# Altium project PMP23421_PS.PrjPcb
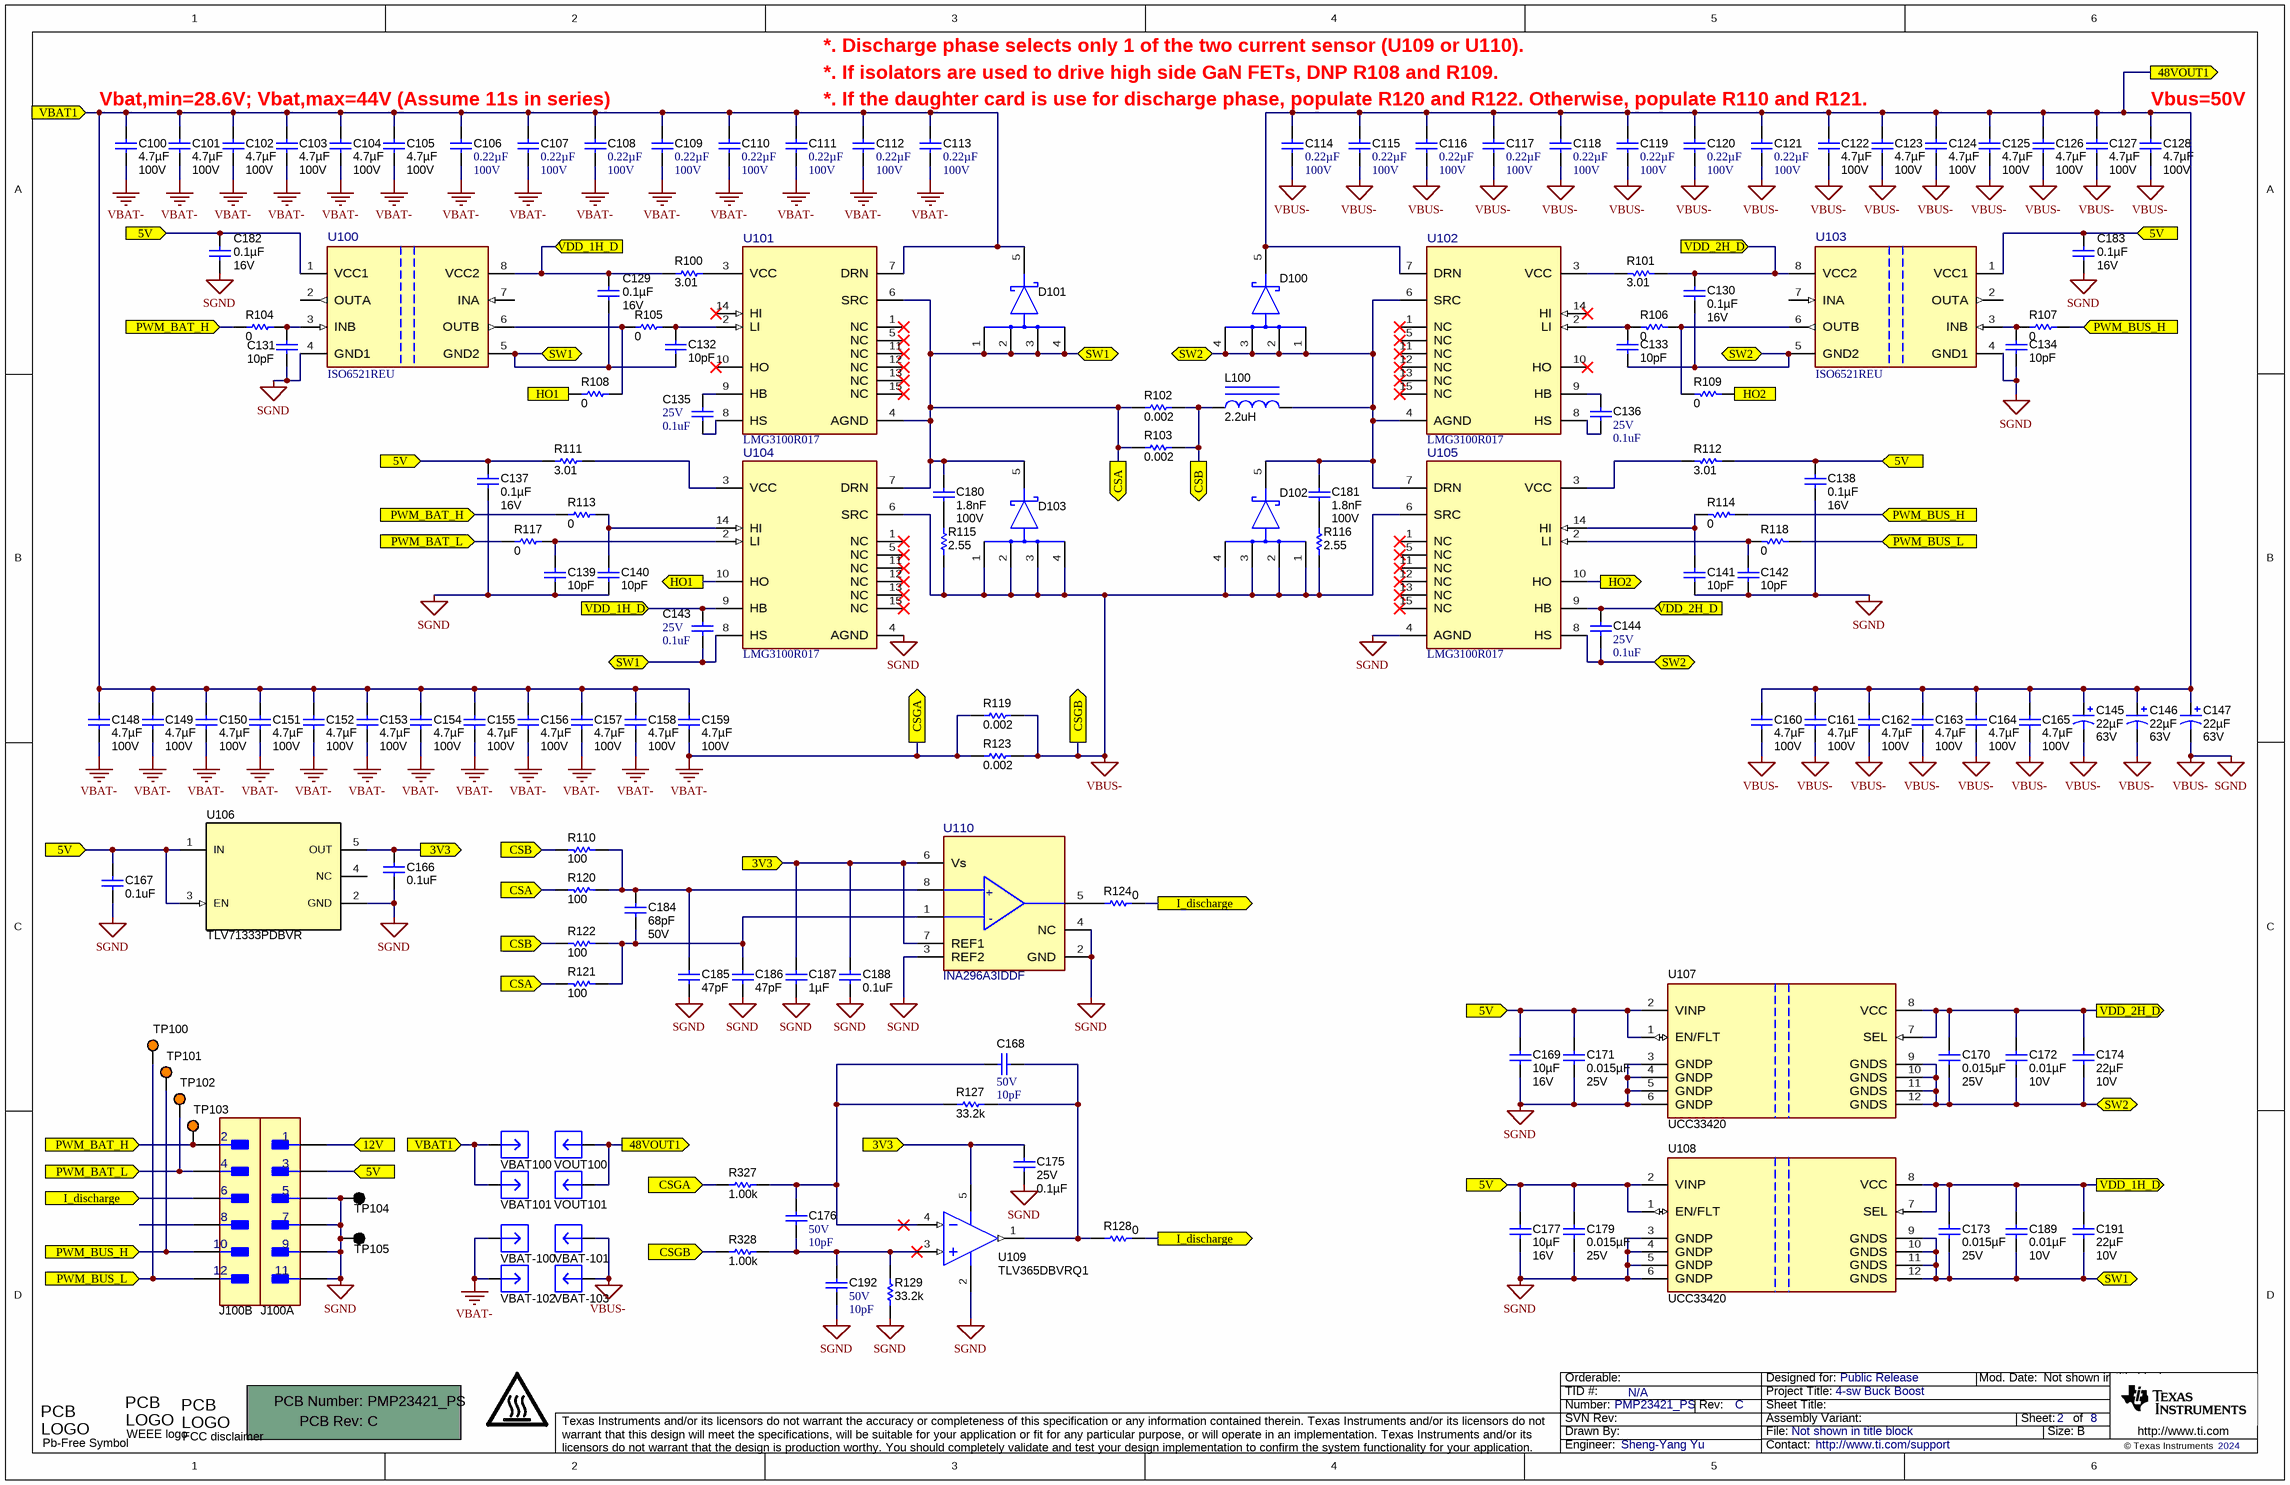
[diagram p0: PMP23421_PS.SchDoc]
CopyrightYear: 2024; PCB_Layout: Sheng-Yang Yu; PCB_Rev: C; PRJ_Customer: Public Release; PRJ_Engineer: Sheng-Yang Yu; PRJ_Number: PMP23421_PS; PRJ_Title: 4-sw Buck Boost; SCH_Rev: C; TechSupport: http://www.ti.com/support; TID: N/A
1 sheet, 157 parts. Net scope: flat (ports and power ports of the same name join across sheets).
Board file: PMP23421_PS.PcbDoc

## Sheet PMP23421_PS.SchDoc
size 431 x 279 mm; Date: Not shown in title block; ApprovedBy: Not shown in title block; CheckedBy: Not shown in title block; Author: Not shown in title block; CompanyName: Not shown in title block; Engineer: Not shown in title block; Organization: Not shown in title block; Address1: Not shown in title block; Address2: Not shown in title block; Address3: Not shown in title block; Address4: Not shown in title block; DocumentNumber: 2; Revision: Use project parameter SCH_Rev; SheetNumber: 2; SheetTotal: 8; PageSetup: Record=PageOptions¦CenterHorizontal=True¦CenterVertical=True¦PrintScale=1.00¦XCorrection=1.00¦YCorrection=1.00¦PrintKind=0¦BorderSize=5000000¦LeftOffset=0¦BottomOffset=0¦Orientation=2¦PaperLength=1000¦PaperWidth=1000¦Scale=100¦PaperSource=15¦PrintQuality=600¦MediaType=1¦DitherType=10¦PaperKind=Letter¦PrintScaleMode=1

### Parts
!PCB100  Printed Circuit Board  (value not drawn)  (mechanical)
C100  ValueDisplayed: 4.7µF  Value2: 100V  [1206_180]  (hidden comment: GRJ31CC72A475KE01L)
C101  ValueDisplayed: 4.7µF  Value2: 100V  [1206_180]  (hidden comment: GRJ31CC72A475KE01L)
C102  ValueDisplayed: 4.7µF  Value2: 100V  [1206_180]  (hidden comment: GRJ31CC72A475KE01L)
C103  ValueDisplayed: 4.7µF  Value2: 100V  [1206_180]  (hidden comment: GRJ31CC72A475KE01L)
C104  ValueDisplayed: 4.7µF  Value2: 100V  [1206_180]  (hidden comment: GRJ31CC72A475KE01L)
C105  ValueDisplayed: 4.7µF  Value2: 100V  [1206_180]  (hidden comment: GRJ31CC72A475KE01L)
C106  ValueDisplayed: 0.22µF  Value2: 100V  [0603]  (hidden comment: MBASH168SC7224KTCA01)
C107  ValueDisplayed: 0.22µF  Value2: 100V  [0603]  (hidden comment: MBASH168SC7224KTCA01)
C108  ValueDisplayed: 0.22µF  Value2: 100V  [0603]  (hidden comment: MBASH168SC7224KTCA01)
C109  ValueDisplayed: 0.22µF  Value2: 100V  [0603]  (hidden comment: MBASH168SC7224KTCA01)
C110  ValueDisplayed: 0.22µF  Value2: 100V  [0603]  (hidden comment: MBASH168SC7224KTCA01)
C111  ValueDisplayed: 0.22µF  Value2: 100V  [0603]  (hidden comment: MBASH168SC7224KTCA01)
C112  ValueDisplayed: 0.22µF  Value2: 100V  [0603]  (hidden comment: MBASH168SC7224KTCA01)
C113  ValueDisplayed: 0.22µF  Value2: 100V  [0603]  (hidden comment: MBASH168SC7224KTCA01)
C114  ValueDisplayed: 0.22µF  Value2: 100V  [0603]  (hidden comment: MBASH168SC7224KTCA01)
C115  ValueDisplayed: 0.22µF  Value2: 100V  [0603]  (hidden comment: MBASH168SC7224KTCA01)
C116  ValueDisplayed: 0.22µF  Value2: 100V  [0603]  (hidden comment: MBASH168SC7224KTCA01)
C117  ValueDisplayed: 0.22µF  Value2: 100V  [0603]  (hidden comment: MBASH168SC7224KTCA01)
C118  ValueDisplayed: 0.22µF  Value2: 100V  [0603]  (hidden comment: MBASH168SC7224KTCA01)
C119  ValueDisplayed: 0.22µF  Value2: 100V  [0603]  (hidden comment: MBASH168SC7224KTCA01)
C120  ValueDisplayed: 0.22µF  Value2: 100V  [0603]  (hidden comment: MBASH168SC7224KTCA01)
C121  ValueDisplayed: 0.22µF  Value2: 100V  [0603]  (hidden comment: MBASH168SC7224KTCA01)
C122  ValueDisplayed: 4.7µF  Value2: 100V  [1206_180]  (hidden comment: GRJ31CC72A475KE01L)
C123  ValueDisplayed: 4.7µF  Value2: 100V  [1206_180]  (hidden comment: GRJ31CC72A475KE01L)
C124  ValueDisplayed: 4.7µF  Value2: 100V  [1206_180]  (hidden comment: GRJ31CC72A475KE01L)
C125  ValueDisplayed: 4.7µF  Value2: 100V  [1206_180]  (hidden comment: GRJ31CC72A475KE01L)
C126  ValueDisplayed: 4.7µF  Value2: 100V  [1206_180]  (hidden comment: GRJ31CC72A475KE01L)
C127  ValueDisplayed: 4.7µF  Value2: 100V  [1206_180]  (hidden comment: GRJ31CC72A475KE01L)
C128  ValueDisplayed: 4.7µF  Value2: 100V  [1206_180]  (hidden comment: GRJ31CC72A475KE01L)
C129  ValueDisplayed: 0.1µF  Value2: 16V  [0402]  (hidden comment: 0402YC104KAT2A)
C130  ValueDisplayed: 0.1µF  Value2: 16V  [0402]  (hidden comment: 0402YC104KAT2A)
C131  ValueDisplayed: 10pF  [0402]  (hidden comment: GRM1555C1H100JA01D)
C132  ValueDisplayed: 10pF  [0402]  (hidden comment: GRM1555C1H100JA01D)
C133  ValueDisplayed: 10pF  [0402]  (hidden comment: GRM1555C1H100JA01D)
C134  ValueDisplayed: 10pF  [0402]  (hidden comment: GRM1555C1H100JA01D)
C135  VDC_V: 25V  ValueDisplayed: 0.1uF  [0201_033]  (hidden comment: GRM033R61E104KE14J)
C136  VDC_V: 25V  ValueDisplayed: 0.1uF  [0201_033]  (hidden comment: GRM033R61E104KE14J)
C137  ValueDisplayed: 0.1µF  Value2: 16V  [0402]  (hidden comment: 0402YC104KAT2A)
C138  ValueDisplayed: 0.1µF  Value2: 16V  [0402]  (hidden comment: 0402YC104KAT2A)
C139  ValueDisplayed: 10pF  [0402]  (hidden comment: GRM1555C1H100JA01D)
C140  ValueDisplayed: 10pF  [0402]  (hidden comment: GRM1555C1H100JA01D)
C141  ValueDisplayed: 10pF  [0402]  (hidden comment: GRM1555C1H100JA01D)
C142  ValueDisplayed: 10pF  [0402]  (hidden comment: GRM1555C1H100JA01D)
C143  VDC_V: 25V  ValueDisplayed: 0.1uF  [0201_033]  (hidden comment: GRM033R61E104KE14J)
C144  VDC_V: 25V  ValueDisplayed: 0.1uF  [0201_033]  (hidden comment: GRM033R61E104KE14J)
C145  ValueDisplayed: 22µF  Value2: 63V  [SM_RADIAL_D]  (hidden comment: 63PFV22M6.3X8)
C146  ValueDisplayed: 22µF  Value2: 63V  [SM_RADIAL_D]  (hidden comment: 63PFV22M6.3X8)
C147  ValueDisplayed: 22µF  Value2: 63V  [SM_RADIAL_D]  (hidden comment: 63PFV22M6.3X8)
C148  ValueDisplayed: 4.7µF  Value2: 100V  [1206_180]  (hidden comment: GRJ31CC72A475KE01L)
C149  ValueDisplayed: 4.7µF  Value2: 100V  [1206_180]  (hidden comment: GRJ31CC72A475KE01L)
C150  ValueDisplayed: 4.7µF  Value2: 100V  [1206_180]  (hidden comment: GRJ31CC72A475KE01L)
C151  ValueDisplayed: 4.7µF  Value2: 100V  [1206_180]  (hidden comment: GRJ31CC72A475KE01L)
C152  ValueDisplayed: 4.7µF  Value2: 100V  [1206_180]  (hidden comment: GRJ31CC72A475KE01L)
C153  ValueDisplayed: 4.7µF  Value2: 100V  [1206_180]  (hidden comment: GRJ31CC72A475KE01L)
C154  ValueDisplayed: 4.7µF  Value2: 100V  [1206_180]  (hidden comment: GRJ31CC72A475KE01L)
C155  ValueDisplayed: 4.7µF  Value2: 100V  [1206_180]  (hidden comment: GRJ31CC72A475KE01L)
C156  ValueDisplayed: 4.7µF  Value2: 100V  [1206_180]  (hidden comment: GRJ31CC72A475KE01L)
C157  ValueDisplayed: 4.7µF  Value2: 100V  [1206_180]  (hidden comment: GRJ31CC72A475KE01L)
C158  ValueDisplayed: 4.7µF  Value2: 100V  [1206_180]  (hidden comment: GRJ31CC72A475KE01L)
C159  ValueDisplayed: 4.7µF  Value2: 100V  [1206_180]  (hidden comment: GRJ31CC72A475KE01L)
C160  ValueDisplayed: 4.7µF  Value2: 100V  [1206_180]  (hidden comment: GRJ31CC72A475KE01L)
C161  ValueDisplayed: 4.7µF  Value2: 100V  [1206_180]  (hidden comment: GRJ31CC72A475KE01L)
C162  ValueDisplayed: 4.7µF  Value2: 100V  [1206_180]  (hidden comment: GRJ31CC72A475KE01L)
C163  ValueDisplayed: 4.7µF  Value2: 100V  [1206_180]  (hidden comment: GRJ31CC72A475KE01L)
C164  ValueDisplayed: 4.7µF  Value2: 100V  [1206_180]  (hidden comment: GRJ31CC72A475KE01L)
C165  ValueDisplayed: 4.7µF  Value2: 100V  [1206_180]  (hidden comment: GRJ31CC72A475KE01L)
C166  ValueDisplayed: 0.1uF  [0402]  (hidden comment: GRM155R70J104KA01D)
C167  ValueDisplayed: 0.1uF  [0402]  (hidden comment: GRM155R70J104KA01D)
C168  VDC_V: 50V  ValueDisplayed: 10pF  [0402]  (hidden comment: 04025U100CAT2A)
C169  ValueDisplayed: 10µF  Value2: 16V  [0805_HV]  (hidden comment: GRM21BC71C106KE11L)
C170  ValueDisplayed: 0.015µF  Value2: 25V  [0402]  (hidden comment: GCM155R71E153KA55D)
C171  ValueDisplayed: 0.015µF  Value2: 25V  [0402]  (hidden comment: GCM155R71E153KA55D)
C172  ValueDisplayed: 0.01µF  Value2: 10V  [0402]  (hidden comment: 0402ZC103KAT2A)
C173  ValueDisplayed: 0.015µF  Value2: 25V  [0402]  (hidden comment: GCM155R71E153KA55D)
C174  Cap_F: 22µF  VDC_V: 10V  [0805_HV]  (hidden comment: GRM21BZ71A226ME15L)
C175  VDC_V: 25V  ValueDisplayed: 0.1µF  [0402]  (hidden comment: CGA2B3X7R1E104K050BB)
C176  VDC_V: 50V  ValueDisplayed: 10pF  [0402]  (hidden comment: 04025U100CAT2A)
C177  ValueDisplayed: 10µF  Value2: 16V  [0805_HV]  (hidden comment: GRM21BC71C106KE11L)
C179  ValueDisplayed: 0.015µF  Value2: 25V  [0402]  (hidden comment: GCM155R71E153KA55D)
C180  Cap_F: 1.8nF  VDC_V: 100V  [0603]  (hidden comment: GRM188R72A182KA01D)
C181  Cap_F: 1.8nF  VDC_V: 100V  [0603]  (hidden comment: GRM188R72A182KA01D)
C182  ValueDisplayed: 0.1µF  Value2: 16V  [0402]  (hidden comment: 0402YC104KAT2A)
C183  ValueDisplayed: 0.1µF  Value2: 16V  [0402]  (hidden comment: 0402YC104KAT2A)
C184  ValueDisplayed: 68pF  Value2: 50V  [0603]  (hidden comment: 06035A680JAT2A)
C185  ValueDisplayed: 47pF  [0402]  (hidden comment: GRM1555C1H470FA01D)
C186  ValueDisplayed: 47pF  [0402]  (hidden comment: GRM1555C1H470FA01D)
C187  ValueDisplayed: 1µF  [0603]  (hidden comment: C1608X7R1C105K080AC)
C188  ValueDisplayed: 0.1uF  [0402]  (hidden comment: GRM155R70J104KA01D)
C189  ValueDisplayed: 0.01µF  Value2: 10V  [0402]  (hidden comment: 0402ZC103KAT2A)
C191  Cap_F: 22µF  VDC_V: 10V  [0805_HV]  (hidden comment: GRM21BZ71A226ME15L)
C192  VDC_V: 50V  ValueDisplayed: 10pF  [0402]  (hidden comment: 04025U100CAT2A)
D100  STPS30M100DJF-TR  [FP-STPS30M100DJF-TR_PowerFlat6-MFG]  (value not drawn)
D101  STPS30M100DJF-TR  [FP-STPS30M100DJF-TR_PowerFlat6-MFG]  (value not drawn)
D102  STPS30M100DJF-TR  [FP-STPS30M100DJF-TR_PowerFlat6-MFG]  (value not drawn)
D103  STPS30M100DJF-TR  [FP-STPS30M100DJF-TR_PowerFlat6-MFG]  (value not drawn)
J100  M50-3900642  [FP-M50-3900642_HDR12-MFG]  (value not drawn)  (parts A,B of 2)
L100  ValueDisplayed: 2.2uH  [IHLP8787MZ]  (hidden comment: IHLP8787MZER2R2M5A)
LOGO100  CAUTION HOT SURFACE  [IEC_HotSurface_Small]  (value not drawn)  (no BOM)
Logo101  Pb-Free Symbol  [Pb-Free_Overlay_Medium]  (no BOM)
Logo102  WEEE logo  [WEEE_Minimum]  (no BOM)
Logo103  FCC disclaimer  [FCC_disclaimer]  (no BOM)
R100  ValueDisplayed: 3.01  [0402]  (hidden comment: CRCW04023R01FKED)
R101  ValueDisplayed: 3.01  [0402]  (hidden comment: CRCW04023R01FKED)
R102  ValueDisplayed: 0.002  [0508]  (hidden comment: KRL2012E-M-R002-G-T5)
R103  ValueDisplayed: 0.002  [0508]  (hidden comment: KRL2012E-M-R002-G-T5)
R104  ValueDisplayed: 0  [0402]  (hidden comment: CRCW04020000Z0ED)
R105  ValueDisplayed: 0  [0402]  (hidden comment: CRCW04020000Z0ED)
R106  ValueDisplayed: 0  [0402]  (hidden comment: CRCW04020000Z0ED)
R107  ValueDisplayed: 0  [0402]  (hidden comment: CRCW04020000Z0ED)
R108  ValueDisplayed: 0  [0402]  (hidden comment: CRCW04020000Z0ED)
R109  ValueDisplayed: 0  [0402]  (hidden comment: CRCW04020000Z0ED)
R110  ValueDisplayed: 100  [0603]  (hidden comment: RC0603FR-07100RL)
R111  ValueDisplayed: 3.01  [0402]  (hidden comment: CRCW04023R01FKED)
R112  ValueDisplayed: 3.01  [0402]  (hidden comment: CRCW04023R01FKED)
R113  ValueDisplayed: 0  [0402]  (hidden comment: CRCW04020000Z0ED)
R114  ValueDisplayed: 0  [0402]  (hidden comment: CRCW04020000Z0ED)
R115  ValueDisplayed: 2.55  [1206]  (hidden comment: CRCW12062R55FKEA)
R116  ValueDisplayed: 2.55  [1206]  (hidden comment: CRCW12062R55FKEA)
R117  ValueDisplayed: 0  [0402]  (hidden comment: CRCW04020000Z0ED)
R118  ValueDisplayed: 0  [0402]  (hidden comment: CRCW04020000Z0ED)
R119  ValueDisplayed: 0.002  [0508]  (hidden comment: KRL2012E-M-R002-G-T5)
R120  ValueDisplayed: 100  [0603]  (hidden comment: RC0603FR-07100RL)
R121  ValueDisplayed: 100  [0603]  (hidden comment: RC0603FR-07100RL)
R122  ValueDisplayed: 100  [0603]  (hidden comment: RC0603FR-07100RL)
R123  ValueDisplayed: 0.002  [0508]  (hidden comment: KRL2012E-M-R002-G-T5)
R124  ValueDisplayed: 0  [0402]  (hidden comment: CRCW04020000Z0ED)
R127  ValueDisplayed: 33.2k  [0402]  (hidden comment: CRCW040233K2FKED)
R128  ValueDisplayed: 0  [0402]  (hidden comment: CRCW04020000Z0ED)
R129  ValueDisplayed: 33.2k  [0402]  (hidden comment: CRCW040233K2FKED)
R327  ValueDisplayed: 1.00k  [0402]  (hidden comment: CRCW04021K00FKED)
R328  ValueDisplayed: 1.00k  [0402]  (hidden comment: CRCW04021K00FKED)
TP100  5003  [Keystone5003]  (value not drawn)
TP101  5003  [Keystone5003]  (value not drawn)
TP102  5003  [Keystone5003]  (value not drawn)
TP103  5003  [Keystone5003]  (value not drawn)
TP104  5001  [Keystone5001]  (value not drawn)
TP105  5001  [Keystone5001]  (value not drawn)
U100  ISO6521REU  [REU0008A-MFG]
U101  LMG3100R017  [VBE0015A-MFG]
U102  LMG3100R017  [VBE0015A-MFG]
U103  ISO6521REU  [REU0008A-MFG]
U104  LMG3100R017  [VBE0015A-MFG]
U105  LMG3100R017  [VBE0015A-MFG]
U106  TLV71333PDBVR  [DBV0005A_N]
U107  UCC33420  [RAQ0012B-MFG]
U108  UCC33420  [RAQ0012B-MFG]
U109  TLV365DBVRQ1  [DBV0005A-MFG]
U110  INA296A3IDDF  [DDF0008A-MFG]
VBAT100  3620-2-32-15-00-00-08-0  [Mill-Max_3620-2-32-xx-00-00-08-0]  (value not drawn)
VBAT101  3620-2-32-15-00-00-08-0  [Mill-Max_3620-2-32-xx-00-00-08-0]  (value not drawn)
VBAT-100  3620-2-32-15-00-00-08-0  [Mill-Max_3620-2-32-xx-00-00-08-0]  (value not drawn)
VBAT-101  3620-2-32-15-00-00-08-0  [Mill-Max_3620-2-32-xx-00-00-08-0]  (value not drawn)
VBAT-102  3620-2-32-15-00-00-08-0  [Mill-Max_3620-2-32-xx-00-00-08-0]  (value not drawn)
VBAT-103  3620-2-32-15-00-00-08-0  [Mill-Max_3620-2-32-xx-00-00-08-0]  (value not drawn)
VOUT100  3620-2-32-15-00-00-08-0  [Mill-Max_3620-2-32-xx-00-00-08-0]  (value not drawn)
VOUT101  3620-2-32-15-00-00-08-0  [Mill-Max_3620-2-32-xx-00-00-08-0]  (value not drawn)

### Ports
3V3 (in), 3V3 (out), 5V (in), 12V (in), 48VOUT1 (out), CSA (in), CSA (out), CSB (in), CSB (out), CSGA (in), CSGA (out), CSGB (in), CSGB (out), HO1 (in), HO1 (out), HO2 (in), HO2 (out), I_discharge (in), I_discharge (out), PWM_BAT_H (in), PWM_BAT_L (in), PWM_BUS_H (in), PWM_BUS_L (in), SW1 (bidir), SW2 (bidir), VBAT1 (in), VDD_1H_D (in), VDD_1H_D (out), VDD_2H_D (in), VDD_2H_D (out)

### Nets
SGND: C114.2 C115.2 C116.2 C117.2 C118.2 C119.2 C120.2 C121.2 C122.2 C123.2 C124.2 C125.2 C126.2 C127.2 C128.2 C131.1 C134.1 C137.2 C138.2 C139.2 C140.2 C141.2 C142.2 C145.2(-) C146.2(-) C147.2(-) C160.2 C161.2 C162.2 C163.2 C164.2 C165.2 C166.2 C167.2 C169.2 C171.2 C175.2 C177.2 C179.2 C182.2 C183.2 C185.2 C186.2 C187.2 C188.2 C192.2 D102.1(A) D102.2(A) D102.3(A) D102.4(A) D103.1(A) D103.2(A) D103.3(A) D103.4(A) J100.5 J100.7 J100.9 J100.11 R115.1 R116.2 R119.2 R123.2 R129.1 R328.1 TP104.1 TP105.1 U100.4(GND1) U103.4(GND1) U104.4(AGND) U104.6(SRC) U105.4(AGND) U105.6(SRC) U106.2(GND) U107.3(GNDP) U107.4(GNDP) U107.5(GNDP) U107.6(GNDP) U108.3(GNDP) U108.4(GNDP) U108.5(GNDP) U108.6(GNDP) U109.2(V-) U110.2(GND) U110.3(REF2) U110.4(NC) VBAT-101.1 VBAT-103.1 ; port CSGB  [also labelled VBUS-]
VBAT-: C100.2 C101.2 C102.2 C103.2 C104.2 C105.2 C106.2 C107.2 C108.2 C109.2 C110.2 C111.2 C112.2 C113.2 C148.2 C149.2 C150.2 C151.2 C152.2 C153.2 C154.2 C155.2 C156.2 C157.2 C158.2 C159.2 R119.1 R123.1 R327.1 VBAT-100.1 VBAT-102.1 ; port CSGA
3V3: C166.1 C175.1 C187.1 C188.1 U106.5(OUT) U109.5(V+) U110.6(Vs) U110.7(REF1) ; port 3V3
5V: C137.1 C138.1 C167.1 C169.1 C171.1 C177.1 C179.1 C182.1 C183.1 J100.3 R111.1 R112.1 U100.1(VCC1) U103.1(VCC1) U106.1(IN) U106.3(EN) U107.1(EN/FLT) U107.2(VINP) U108.1(EN/FLT) U108.2(VINP) ; port 5V
12V: J100.1 ; port 12V
48VOUT1: C114.1 C115.1 C116.1 C117.1 C118.1 C119.1 C120.1 C121.1 C122.1 C123.1 C124.1 C125.1 C126.1 C127.1 C128.1 C145.1(+) C146.1(+) C147.1(+) C160.1 C161.1 C162.1 C163.1 C164.1 C165.1 D100.5(K) U102.7(DRN) VOUT100.1 VOUT101.1 ; port 48VOUT1
CSA: C129.2 C132.2 C143.2 C173.2 C180.1 C189.2 C191.2 D101.1(A) D101.2(A) D101.3(A) D101.4(A) D103.5(K) R102.1 R103.1 R120.2 R121.2 U100.5(GND2) U101.4(AGND) U101.6(SRC) U104.7(DRN) U104.8(HS) U108.9(GNDS) U108.10(GNDS) U108.11(GNDS) U108.12(GNDS) ; port SW1, port CSA
CSB: L100.1 R102.2 R103.2 R110.2 R122.2 ; port CSB
HO1: R108.1 U104.10(HO) ; port HO1
HO2: R109.1 U105.10(HO) ; port HO2
I_discharge: J100.6 R124.2 R128.2 ; port I_discharge
PWM_BAT_H: J100.2 R104.1 R113.1 TP103.1 ; port PWM_BAT_H
PWM_BAT_L: J100.4 R117.1 TP102.1 ; port PWM_BAT_L
PWM_BUS_H: J100.10 R107.2 R114.1 TP101.1 ; port PWM_BUS_H
PWM_BUS_L: J100.12 R118.1 TP100.1 ; port PWM_BUS_L
SW2: C130.2 C133.2 C144.2 C170.2 C172.2 C174.2 C181.1 D100.1(A) D100.2(A) D100.3(A) D100.4(A) D102.5(K) L100.2 U102.4(AGND) U102.6(SRC) U103.5(GND2) U105.7(DRN) U105.8(HS) U107.9(GNDS) U107.10(GNDS) U107.11(GNDS) U107.12(GNDS) ; port SW2
VBAT1: C100.1 C101.1 C102.1 C103.1 C104.1 C105.1 C106.1 C107.1 C108.1 C109.1 C110.1 C111.1 C112.1 C113.1 C148.1 C149.1 C150.1 C151.1 C152.1 C153.1 C154.1 C155.1 C156.1 C157.1 C158.1 C159.1 D101.5(K) U101.7(DRN) VBAT100.1 VBAT101.1 ; port VBAT1
VDD_1H_D: C129.1 C143.1 C173.1 C189.1 C191.1 R100.1 U100.8(VCC2) U104.9(HB) U108.7(SEL) U108.8(VCC) ; port VDD_1H_D
VDD_2H_D: C130.1 C144.1 C170.1 C172.1 C174.1 R101.1 U103.8(VCC2) U105.9(HB) U107.7(SEL) U107.8(VCC) ; port VDD_2H_D
NetC131_2: C131.2 R104.2 U100.3(INB)
NetC132_1: C132.1 R105.2 U101.2(LI)
NetC133_1: C133.1 R106.2 U102.2(LI)
NetC134_2: C134.2 R107.1 U103.3(INB)
NetC135_1: C135.1 U101.9(HB)
NetC135_2: C135.2 U101.8(HS)
NetC136_1: C136.1 U102.9(HB)
NetC136_2: C136.2 U102.8(HS)
NetC139_1: C139.1 R117.2 U104.2(LI)
NetC140_1: C140.1 R113.2 U104.14(HI)
NetC141_1: C141.1 R114.2 U105.14(HI)
NetC142_1: C142.1 R118.2 U105.2(LI)
NetC168_1: C168.1 R127.1 R128.1 U109.1(VOUT)
NetC168_2: C168.2 C176.1 R127.2 R327.2 U109.4(-IN)
NetC176_2: C176.2 C192.1 R129.2 R328.2 U109.3(+IN)
NetC180_2: C180.2 R115.2
NetC181_2: C181.2 R116.1
NetC184_1: C184.1 C185.1 R110.1 R120.1 U110.8(IN+)
NetC184_2: C184.2 C186.1 R121.1 R122.1 U110.1(IN-)
NetR100_2: R100.2 U101.3(VCC)
NetR101_2: R101.2 U102.3(VCC)
NetR105_1: R105.1 R108.2 U100.6(OUTB)
NetR106_1: R106.1 R109.2 U103.6(OUTB)
NetR111_2: R111.2 U104.3(VCC)
NetR112_2: R112.2 U105.3(VCC)
NetR124_1: R124.1 U110.5(OUT)

Not connected (* = marked no-connect by the designer): J100 8; U100 2(OUTA) 7(INA); U101 1(NC)* 5(NC)* 10(HO)* 11(NC)* 12(NC)* 13(NC)* 14(HI)* 15(NC)*; U102 1(NC)* 5(NC)* 10(HO)* 11(NC)* 12(NC)* 13(NC)* 14(HI)* 15(NC)*; U103 2(OUTA) 7(INA); U104 1(NC)* 5(NC)* 11(NC)* 12(NC)* 13(NC)* 15(NC)*; U105 1(NC)* 5(NC)* 11(NC)* 12(NC)* 13(NC)* 15(NC)*; U106 4(NC)

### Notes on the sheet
- Vbat,min=28.6V; Vbat,max=44V (Assume 11s in series)
- *. If isolators are used to drive high side GaN FETs, DNP R108 and R109.
- *. Discharge phase selects only 1 of the two current sensor (U109 or U110).
- *. If the daughter card is use for discharge phase, populate R120 and R122. Otherwise, populate R110 and R121.
- (near C128) Vbus=50V

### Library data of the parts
!PCB100 = CMP-0003618-2: Manufacturer: Any; PartNumber: PMP23421_PS
C100-C105 C122-C128 C148-C165 = C3216X6S1H475K160AB: CAP CER 4.7UF 100V X7S 1206; Polarized: N; CompType: Capacitor; U/M: EA; Cap_F: 0.0000047; Tolerance_%: 10; VDC_V: 100; TaMin_C: -55; TaMax_C: 105; Cap_Case: 1206; SizeArea_mm2: 5.12; SizeAreaWB_mm2: 10.92; SizeX_mm: 3.2; SizeY_mm: 1.6; SizeZ_mm: 1.8; AEC Category: Q200
C106-C121 = CMP-0077894-3: CAP, CERM, 0.22 µF, 100 V,+/- 10%, X7S, AEC-Q200 Grade 1, 0603; Manufacturer: Taiyo Yuden; Polarized: N; CompType: Capacitor; Value: 0.22uF; U/M: EA; Cap_F: 220nF; TaMin_C: -55°C; TaMax_C: 125°C; SizeArea_mm2: 1.28; SizeAreaWB_mm2: 4.68; SizeX_mm: 1.6; SizeY_mm: 0.8; AEC Category: Q200; AEC Qualified: Y; AEC Grade: 1
C129 C130 C137 C138 C182 C183 = 0402YC104KAT2A: CAP, CERM, 0.1 µF, 16 V,+/- 10%, X7R, 0402; Manufacturer: AVX; Polarized: N; CompType: Capacitor; Value: 0.1uF; U/M: EA; Cap_F: 0.0000001; Tolerance_%: 10; VDC_V: 16; TaMin_C: -55; TaMax_C: 125; SizeArea_mm2: 0.5; SizeAreaWB_mm2: 3; SizeX_mm: 1; SizeZ_mm: 0.6; AEC Category: Q200; Green_Lifecycle: Active; Green_REACh: Passed
C131-C134 C139-C142 = GRM1555C1H100JA01D: CAP, CERM, 10pF, 50V, +/-5%, C0G/NP0, 0402; Manufacturer: MuRata; Polarized: N; CompType: Capacitor; U/M: EA; Cap_F: 0.00000000001; Tolerance_%: 5; Value1: Unknown; VDC_V: 50; TaMin_C: -55; TaMax_C: 125
C135 C136 C143 C144 = CMP-0009719-2: CAP, CERM, 0.1 uF, 25 V, +/- 10%, X5R, 0201; Manufacturer: MuRata; TaMin_C: -55°C; Polarized: N; SizeAreaWB_mm2: 2.08; Value1: Unknown; U/M: EA; Value: 0.1uF; TaMax_C: 85°C; SizeZ_mm: 0.33; SizeX_mm: 0.6; SizeY_mm: 0.3; Cap_Case: 0201; SizeArea_mm2: 0.18; Cap_F: 100nF; AEC Category: Q200
C145-C147 = EEE-FK1H220P: CAP ALUM POLY HYB 22UF 63V SMD; Manufacturer: Rubycon; Polarized: Y; CompType: Capacitor; Cap_F: 0.000022; Tolerance_%: 20; Value1: 0.88 ohm; VDC_V: 63; Cap_Case: D; SizeAreaWB_mm2: 84.28; SizeArea_mm2: 51.48; SizeX_mm: 7.8; SizeY_mm: 6.6; SizeZ_mm: 5.4; Green_Lifecycle: Active; Green_REACh: Passed
C166 C167 = CMP-0006623-2: CAP, CERM, 0.1 uF, 6.3 V, +/- 10%, X7R, 0402; Manufacturer: MuRata; Polarized: N; CompType: Capacitor; Value: 0.1uF; U/M: EA; Cap_F: 100nF; Value1: Unknown; VDC_V: 6.3V; TaMin_C: -55°C; TaMax_C: 125°C; AEC Category: Q200; SizeArea_mm2: 0.5; SizeAreaWB_mm2: 3; SizeX_mm: 1; SizeZ_mm: 0.6
C168 C176 C192 = CMP-0064911-2: CAP, CERM, 10 pF, 50 V,+/- 2.5%, C0G/NP0, AEC-Q200 Grade 1, 0402; Manufacturer: AVX; TaMin_C: -55°C; Polarized: N; SizeAreaWB_mm2: 3; Value1: Unknown; U/M: EA; Value: 10pF; TaMax_C: 125°C; SizeZ_mm: 0.6; SizeX_mm: 1; SizeY_mm: 0.5; CompType: Capacitor; AEC Qualified: Y; AEC Category: Q200
C169 C177 = GRM21BC71C106KE11L: CAP, CERM, 10 µF, 16 V,+/- 10%, X7S, 0805; Manufacturer: MuRata; Polarized: N; CompType: Capacitor; Value: 10uF; U/M: EA; Cap_F: 0.00001; Tolerance_%: 10; VDC_V: 16; TaMin_C: -55; TaMax_C: 125; Cap_Case: 0805; SizeArea_mm2: 2.5; SizeAreaWB_mm2: 6.75; SizeX_mm: 2; SizeY_mm: 1.25; SizeZ_mm: 1.45; AEC Category: Q200
C170 C171 C173 C179 = 0402ZC103KAT2A: CAP CER 0.015UF 25V X7R 0402; Manufacturer: AVX; Polarized: N; CompType: Capacitor; U/M: EA; Cap_F: 0.000000015; Tolerance_%: 10; VDC_V: 25; TaMin_C: -55; TaMax_C: 125; SizeArea_mm2: 0.5; SizeAreaWB_mm2: 3; SizeX_mm: 1; SizeZ_mm: 0.6; AEC Category: Q200
C172 C189 = 0402ZC103KAT2A: CAP, CERM, 0.01 µF, 10 V,+/- 10%, X7R, 0402; Manufacturer: AVX; Polarized: N; CompType: Capacitor; Value: 0.01uF; U/M: EA; Cap_F: 0.00000001; Tolerance_%: 10; TaMin_C: -55; TaMax_C: 125; SizeArea_mm2: 0.5; SizeAreaWB_mm2: 3; SizeX_mm: 1; SizeZ_mm: 0.6; AEC Category: Q200
C174 C191 = CMP-0008377-2: CAP, CERM, 22 uF, 10 V, +/- 20%, X7R, 0805; Manufacturer: MuRata; SizeY_mm: 1.25; Cap_Case: 0805; SizeArea_mm2: 2.5; CompType: Capacitor; AEC Qualified: N; AEC Category: Q200; ValueDisplayed: 22uF; TaMin_C: -55°C; SizeAreaWB_mm2: 6.75; Value1: Unknown; U/M: EA; Value: 22uF; TaMax_C: 125°C; SizeZ_mm: 1.45; SizeX_mm: 2
C175 = CMP-0080610-1: CAP, CERM, 0.1 µF, 25 V,+/- 10%, X7R, AEC-Q200 Grade 1, 0402; Manufacturer: TDK; TaMin_C: -55°C; Polarized: N; SizeAreaWB_mm2: 3; U/M: EA; Value: 0.1uF; TaMax_C: 125°C; SizeZ_mm: 0.6; SizeX_mm: 1; SizeY_mm: 0.5; CompType: Capacitor; AEC Qualified: Y; Cap_F: 100nF; AEC Category: Q200
C180 C181 = CMP-0007473-4: CAP, CERM, 1800 pF, 100 V, +/- 10%, X7R, 0603; Manufacturer: MuRata; TaMin_C: -55°C; Polarized: N; SizeAreaWB_mm2: 4.68; Value1: Unknown; U/M: EA; Value: 1800pF; TaMax_C: 125°C; SizeZ_mm: 1; SizeX_mm: 1.6; SizeY_mm: 0.8; SizeArea_mm2: 1.28; CompType: Capacitor; AEC Category: Q200
C184 = 06035A680JAT2A: CAP, CERM, 68 pF, 50 V,+/- 5%, C0G/NP0, 0603; Manufacturer: AVX; Polarized: N; CompType: Capacitor; Value: 68pF; U/M: EA; Cap_F: 0.000000000068; Tolerance_%: 5; ESR_ohm: 0.144; Value1: 0.144 ohm; VDC_V: 50; TaMin_C: -55; TaMax_C: 125; SizeArea_mm2: 1.28; SizeAreaWB_mm2: 4.68; SizeX_mm: 1.6; SizeY_mm: 0.8; SizeZ_mm: 1; AEC Category: Q200; Green_Lifecycle: Active; Green_REACh: Passed
C185 C186 = GRM1555C1H470FA01D: CAP, CERM, 47 pF, 50 V,+/- 1%, C0G/NP0, 0402; Manufacturer: MuRata; Polarized: N; CompType: Capacitor; Value: 47pF; U/M: EA; Cap_F: 0.000000000047; Tolerance_%: 1; VDC_V: 50; Value2: 50V; TaMin_C: -55; TaMax_C: 125; SizeArea_mm2: 0.5; SizeAreaWB_mm2: 3; SizeZ_mm: 0.6; AEC Category: Q200; Green_Lifecycle: Active; Green_REACh: Passed
C187 = C1608X7R1C105K080AC: CAP, CERM, 1 µF, 16 V,+/- 10%, X7R, 0603; Manufacturer: TDK; Polarized: N; CompType: Capacitor; Value: 1uF; U/M: EA; Cap_F: 0.000001; Tolerance_%: 10; ESR_ohm: 0.0057; Value1: 0.0057 ohm; VDC_V: 16; Value2: 16V; TaMin_C: -55; TaMax_C: 125; SizeArea_mm2: 1.28; SizeAreaWB_mm2: 4.68; SizeX_mm: 1.6; SizeY_mm: 0.8; SizeZ_mm: 1; AEC Category: Q200; Green_Lifecycle: Active; Green_REACh: Passed
C188 = GRM155R70J104KA01D: CAP, CERM, 0.1uF, 6.3V, +/-10%, X7R, 0402; Manufacturer: MuRata; Polarized: N; CompType: Capacitor; U/M: EA; Cap_F: 0.0000001; Tolerance_%: 10; Value1: Unknown; VDC_V: 6.3; TaMin_C: -55; TaMax_C: 125
D100-D103 = CMP-0032275-1: Diode 100 V 30A Surface Mount PowerFlat™ (5x6); Manufacturer: STMicroelectronics; AEC Qualified: No; SizeZ_mm: 1.05mm; TJmax_C: 150°C; Vf_V: 100V; Max Surge Forward Current: 200A; Peak Reverse Current: 100uA; Standoff Height: 0mm
J100 = CMP-0093439-1: Connector Header Through Hole, Right Angle 12 position 0.050" (1.27mm); Manufacturer: Harwin; Conn Gender: Male; Conn Orientation: Horizontal; ContactFinish: Gold,Nickel; Row_Count: 2; SizeZ_mm: 3.55mm; AEC Qualified: No; Current_A: 1A
L100 = CMP-0063542-1: Inductor, Shielded, 2.2 uH, 48 A, 0.00123 ohm, AEC-Q200 Grade 0, SMD; Manufacturer: Vishay-Dale; Isat: 48A @ 20% inductance drop; Irms: 58A @ 40C rise; Green_Lifecycle: Active; SizeAreaWB_mm2: 587.52; DCR_ohm: 1.23m; Green_REACh: Passed; Value: 2.2uH; Imax_A: 48A; SizeZ_mm: 13; SizeX_mm: 22.48; SizeY_mm: 22; SizeArea_mm2: 494.56; Ind_H: 2.2µH; AEC Qualified: Y; AEC Grade: 0; AEC Category: Q200
LOGO100 = CMP-0074837-1: IEC 61010-1 Hot Surface Warning; Library Reference: IEC_HotSurface; SymbolCreator: a0412235
Logo101 = Pb-Free: SymbolCreator: a0412235
Logo102 = CMP-0074769-1
Logo103 = CMP-0074847-1: FCC_disclaimer; Library Reference: Logo
R100 R101 R111 R112 = CRCW04023R01FKED: RES, 3.01, 1%, 0.063 W, 0402; Manufacturer: Vishay-Dale; CompType: Resistor; Value: 3.01; Value_Code: 3R01; Tolerance_%: 1; Power_W: 0.063; Value2: 0.063W; VDC_V: 50; TempCo: 100 ppm/C; SizeArea_mm2: 0.5; SizeZ_mm: 0.6; EIA_Code: E96; U/M: EA; AEC Category: Q200
R102 R103 R119 R123 = CMP-0015357-3: RES, 0.002, 2%, 1 W, 0508; Manufacturer: Susumu Co Ltd; Power_W: 1W; TempCo: 100 ppm/C; SizeAreaWB_mm2: 6.75; Value_Code: 2L000; U/M: EA; Value: 0.002; Res_ohm: 2m; SizeX_mm: 1.25; SizeY_mm: 2; SizeZ_mm: 1; SizeArea_mm2: 2.5; CompType: Resistor; AEC Category: Q200
R104-R109 R113 R114 R117 R118 R124 R128 = CRCW04020000Z0ED: RES, 0, 5%, 0.063 W, 0402; Manufacturer: Vishay-Dale; CompType: Resistor; Value: 0; Value_Code: 0000; Tolerance_%: 5; Power_W: 0.063; Value2: 0.063W; VDC_V: 50; TempCo: 200 ppm/C; SizeArea_mm2: 0.5; SizeX_mm: 1; SizeZ_mm: 0.6; EIA_Code: E24; U/M: EA; AEC Category: Q200; Green_Lifecycle: Active; Green_REACh: Passed
R110 R120-R122 = RC0603FR-07100RL: RES, 100, 1%, 0.1 W, 0603; Manufacturer: Yageo America; CompType: Resistor; Value: 100; Value_Code: 100R; Tolerance_%: 1; Power_W: 0.1; Value2: 0.1W; VDC_V: 150; TempCo: 200 ppm/C; SizeArea_mm2: 1.28; SizeX_mm: 1.6; SizeY_mm: 0.8; EIA_Code: E96; U/M: EA; AEC Category: Q200; Green_Lifecycle: Active; Green_REACh: Passed
R115 R116 = CMP-0016888-3: RES, 2.55, 1%, 0.25 W, AEC-Q200 Grade 0, 1206; Manufacturer: Vishay-Dale; Power_W: 250mW; TempCo: 100 ppm/C; Value_Code: 2R55; Value: 2.55; EIA_Code: E96; SizeX_mm: 3.2; SizeY_mm: 1.6; SizeZ_mm: 1.35; Value2: 0.25W; SizeArea_mm2: 5.12; CompType: Resistor; AEC Qualified: Y; VDC_V: 200V; AEC Category: Q200; AEC Grade: 0
R127 R129 = CRCW040233K2FKED: RES, 33.2 k, 1%, 0.063 W, 0402; Manufacturer: Vishay-Dale; CompType: Resistor; Value: 33.2k; Res_ohm: 33200; Value_Code: 33k2; Tolerance_%: 1; Power_W: 0.063; Value2: 0.063W; VDC_V: 50; TempCo: 100 ppm/C; SizeArea_mm2: 0.5; SizeZ_mm: 0.6; EIA_Code: E96; U/M: EA; AEC Category: Q200
R327 R328 = CMP-0026071-3: RES, 1.00 k, 1%, 0.063 W, AEC-Q200 Grade 0, 0402; Manufacturer: Vishay-Dale; Power_W: 63mW; TempCo: 100 ppm/C; Value_Code: 1k00; Value: 1.00k; EIA_Code: E96; Res_ohm: 1k; SizeX_mm: 1; SizeY_mm: 0.5; SizeZ_mm: 0.6; Value2: 0.063W; AEC Qualified: Y; VDC_V: 50V; AEC Category: Q200; AEC Grade: 0
TP100-TP103 = 5003: Test Point, Miniature, Orange, TH; Manufacturer: Keystone; CompType: Test Point Loop; ContactFinish: Silver; Green_Lifecycle: Active; Green_REACh: Passed
TP104 TP105 = 5001: Test Point, Miniature, Black, TH; Manufacturer: Keystone; CompType: Test Point Loop; ContactFinish: Silver; Green_Lifecycle: Active; Green_REACh: Passed
U100 U103 = CMP-0035039-1: General Purpose Dual-Channel Functional Isolators; Manufacturer: Texas Instruments; Interface: LVCMOS; Max Supply Voltage: 5.5V; Min Supply Voltage: 1.71V; Nominal Supply Current: 1.2-5.2mA; Standoff Height: 0mm; SizeZ_mm: 1.05mm; AEC Qualified: No; TaMax_C: +125°C; TaMin_C: -40°C; TJmax_C: +150°C
U101 U102 U104 U105 = CMP-0037654-1: 100-V, 64-A GaN with Integrated Driver; Manufacturer: Texas Instruments; SizeZ_mm: 0.85mm; AEC Qualified: No; Max Supply Voltage: 5.25V; Min Supply Voltage: 4.75V; Nominal Supply Current: 3mA; Number Of Drivers: 1; Propagation Delay: 55ns; Standoff Height: 0mm; TJmax_C: +125°C
U106 = CMP-0066771-1: 150-mA, Low-Dropout Regulator with Foldback Current Limit for Portable Devices, DBV0005A (SOT-23-5); Alternate PartNumber: TLV71333PDBVT; Alternate Manufacturer: Texas Instruments; Green_Lifecycle: Active; SizeAreaWB_mm2: 14.82; Green_REACh: Passed; U/M: EA; SizeZ_mm: 1.45; SizeX_mm: 2.8; SizeY_mm: 2.9; SizeArea_mm2: 8.12; CompType: IC
U107 U108 = CMP-0098322-4: 1.5W, High-Density, >3 kVRMS Isolated DC-DC Converter; Manufacturer: Texas Instruments; SizeZ_mm: 1.05mm; AEC Qualified: No; AEC Grade: NA; Max Supply Voltage: 5.5V; Min Supply Voltage: 4.5V; Number Of Outputs: 1; Output Type: Fixed; Output Voltage: 5V; AEC Category: Q200; CompType: IC
U109 = CMP-0032028-2: CMOS Amplifier 1 Circuit Rail-to-Rail SOT-23-5; Manufacturer: Texas Instruments; SizeZ_mm: 1.45mm; AEC Qualified: No; Gain Bandwidth: 50MHz; Input Bias Current: 0.000005uA; Input Offset Voltage: 0.4mV; Max Supply Voltage: 5.5V; Min Supply Voltage: 2.2V; Nominal Supply Current: 4.6mA; Number Of Channels: 1; Output Current Per Channel: 85mA; Response Time: 0.2us; Standoff Height: 0mm; TaMax_C: +125°C; TaMin_C: -40°C; TJmax_C: +150°C; Voltage Gain: 120dB; AEC Category: Q200; CompType: IC
U110 = CMP-0093654-2: -4-V to 110-V, Bidirectional, 1-MHz, 5V/μs, Ultra-Precise Current Sense Amplifier, SOT23-8; Manufacturer: Texas Instruments; Voltage Gain: 0.05V/mV; SizeZ_mm: 1.1mm; Nominal Supply Current: 2.5mA; AEC Category: Q200; Bandwidth: 1MHz; Standoff Height: 0mm; TaMin_C: -40°C; Input Bias Current: 40uA; TaMax_C: +125°C; Min Supply Voltage: 2.7V; Input Offset Voltage: 0.002mV; Number Of Channels: 1; AEC Qualified: No; CompType: IC; Response Time: 1.5us; Max Supply Voltage: 20V; TJmax_C: +150°C
VBAT100 VBAT101 VBAT-100-VBAT-103 VOUT100 VOUT101 = CMP-0055044-1: PCB Pin, 0.04" DIA, Edge-Mount; Manufacturer: Mill-Max; CompType: PCB Pin; Gender: Male; Row_Count: 1; ContactFinish: Gold; CNHeader: FALSE

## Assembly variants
001: not fitted C168 C176 C180 C181 C184 C192 D100 D101 R108 R109 R110 R113 R114 R115 R116 R121 R124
